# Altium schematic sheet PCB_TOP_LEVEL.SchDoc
size B; SheetNumber: 1; SheetTotal: 6
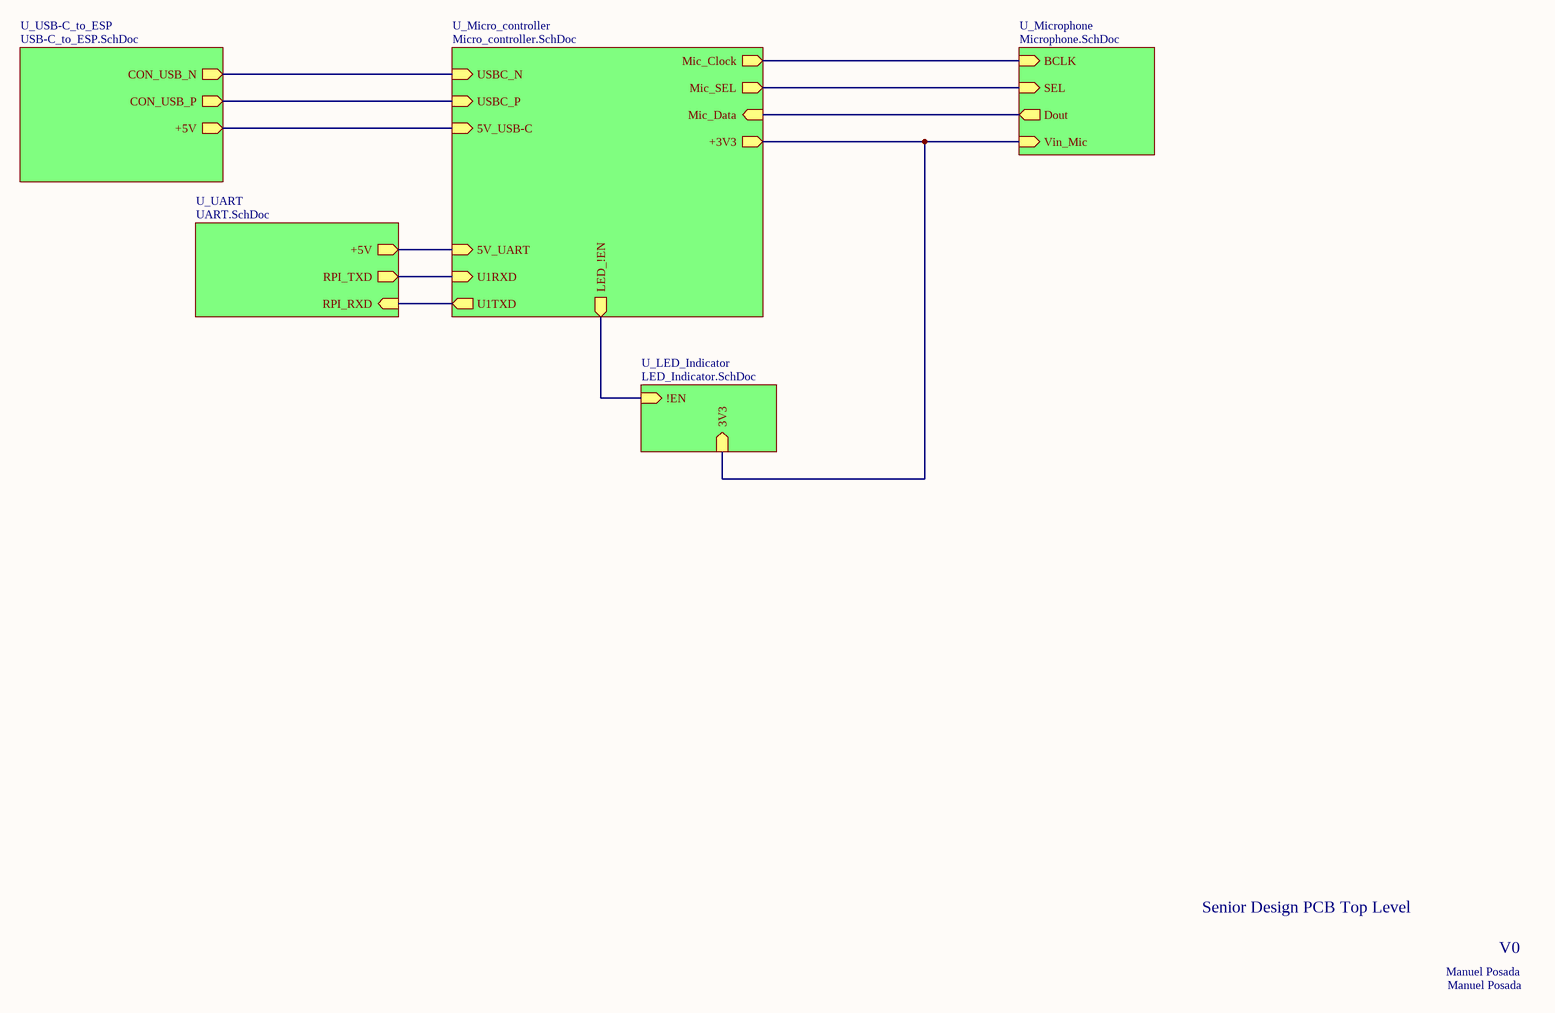
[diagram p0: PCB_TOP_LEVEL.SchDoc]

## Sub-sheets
U_LED_Indicator = LED_Indicator.SchDoc: 3V3 (in), !EN (in)
U_Micro_controller = Micro_controller.SchDoc: Mic_Data (in), Mic_SEL (out), Mic_Clock (out), U1TXD (out), U1RXD (in), LED_!EN (out), USBC_N (in), USBC_P (in), 5V_USB-C (in), 5V_UART (in), +3V3 (out)
U_Microphone = Microphone.SchDoc: Vin_Mic (in), BCLK (in), Dout (out), SEL (in)
U_UART = UART.SchDoc: RPI_RXD (in), RPI_TXD (out), +5V (out)
U_USB-C_to_ESP = USB-C_to_ESP.SchDoc: +5V (out), CON_USB_N (out), CON_USB_P (out)

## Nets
(unnamed): sheet U_Micro_controller/Mic_Data, sheet U_Microphone/Dout
(unnamed): sheet U_Micro_controller/Mic_SEL, sheet U_Microphone/SEL  [a separate net that carries the same name]
(unnamed): sheet U_Micro_controller/Mic_Clock, sheet U_Microphone/BCLK  [a separate net that carries the same name]
(unnamed): sheet U_Micro_controller/U1TXD, sheet U_UART/RPI_RXD  [a separate net that carries the same name]
(unnamed): sheet U_Micro_controller/U1RXD, sheet U_UART/RPI_TXD  [a separate net that carries the same name]
(unnamed): sheet U_Micro_controller/LED_!EN, sheet U_LED_Indicator/!EN  [a separate net that carries the same name]
(unnamed): sheet U_Micro_controller/USBC_N, sheet U_USB-C_to_ESP/CON_USB_N  [a separate net that carries the same name]
(unnamed): sheet U_Micro_controller/USBC_P, sheet U_USB-C_to_ESP/CON_USB_P  [a separate net that carries the same name]
(unnamed): sheet U_Micro_controller/5V_USB-C, sheet U_USB-C_to_ESP/+5V  [a separate net that carries the same name]
(unnamed): sheet U_Micro_controller/5V_UART, sheet U_UART/+5V  [a separate net that carries the same name]
(unnamed): sheet U_Micro_controller/+3V3, sheet U_Microphone/Vin_Mic, sheet U_LED_Indicator/3V3  [a separate net that carries the same name]

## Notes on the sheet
- Senior Design PCB Top Level
- Manuel Posada
- V0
